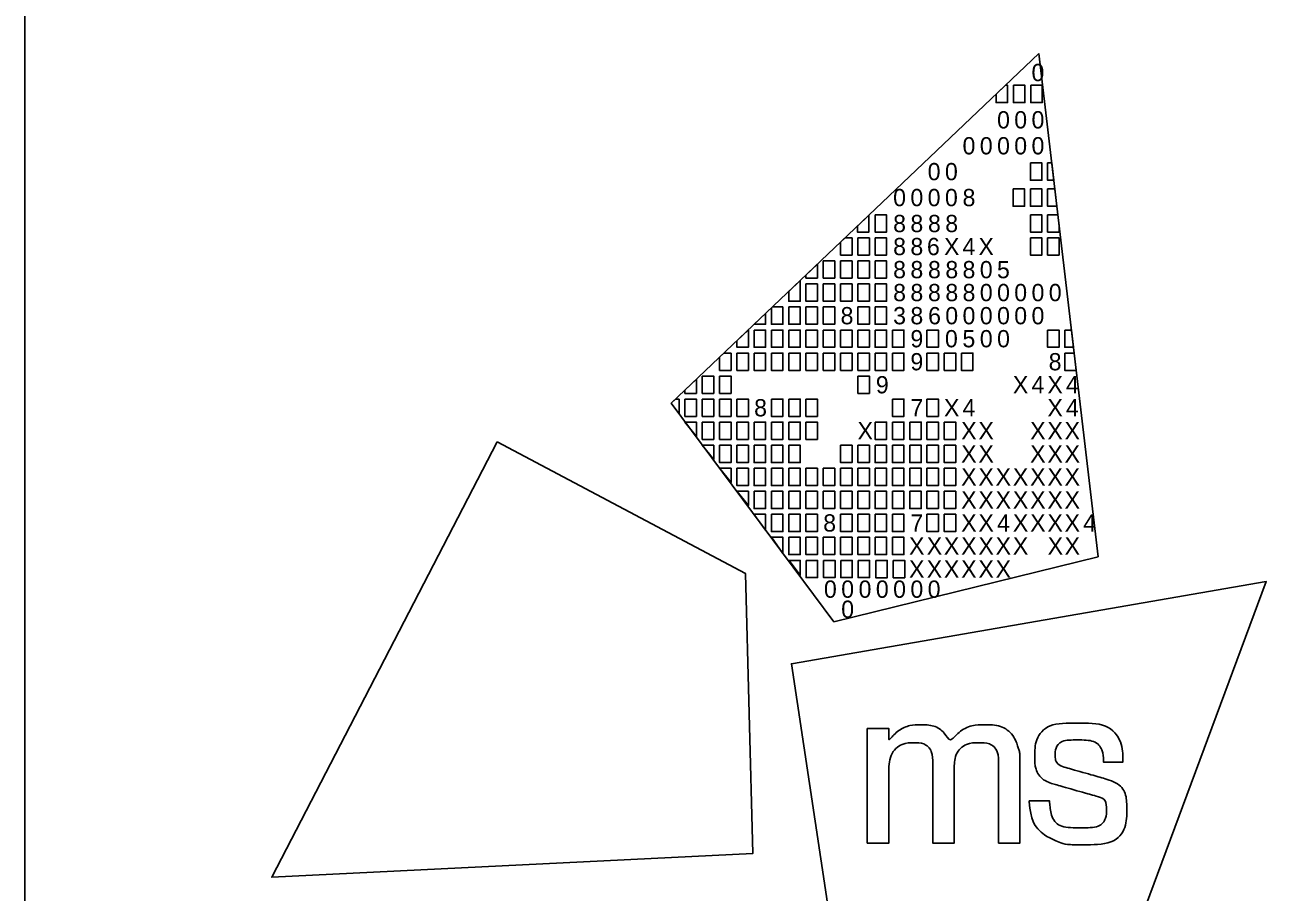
# Model space of a CAD drawing. Extents: x 0 to 34, y 0 to 22.
# Drawn here: x 32 to 33.186, y 3.285 to 4.114 of the extents above; entities that cross this region are included whole.
import ezdxf

# ---------------------------------------------------------------- set-up
doc = ezdxf.new("R2010")
doc.units = 0
doc.layers.add('SH_Border', color=7, linetype='Continuous')
doc.layers.add('SH_Data', color=7, linetype='Continuous')

msp = doc.modelspace()

# ---------------------------------------------------------------- linework, layer by layer
at = {"layer": 'SH_Border'}
msp.add_line((32, 0.5), (32, 21.5), dxfattribs=at)
at = {"layer": 'SH_Data'}
for p, q in [((32.6175, 3.7519), (32.9688, 4.0861)), ((32.9688, 4.0861), (32.9688, 4.0861)), ((32.9688, 4.0861), (33.0253, 3.6052)), ((32.773, 3.543), (32.6175, 3.7519)), ((33.0253, 3.6052), (32.773, 3.543)), ((32.75, 3.5), (32.75, 3.5))]:
    msp.add_line(p, q, dxfattribs=at)
for points in [[(32.9279, 4.0472), (32.9369, 4.0558), (32.9389, 4.0558), (32.9389, 4.0393), (32.9279, 4.0393)], [(32.9444, 4.0558), (32.9554, 4.0558), (32.9554, 4.0393), (32.9444, 4.0393)], [(32.9609, 4.0558), (32.9719, 4.0558), (32.9719, 4.0393), (32.9609, 4.0393)], [(32.9606, 3.9815), (32.9716, 3.9815), (32.9716, 3.965), (32.9606, 3.965)], [(32.9771, 3.9815), (32.9811, 3.9815), (32.983, 3.965), (32.9771, 3.965)], [(32.9441, 3.9567), (32.9551, 3.9567), (32.9551, 3.9402), (32.9441, 3.9402)], [(32.9606, 3.9567), (32.9716, 3.9567), (32.9716, 3.9402), (32.9606, 3.9402)], [(32.9771, 3.9567), (32.984, 3.9567), (32.9859, 3.9402), (32.9771, 3.9402)], [(32.7953, 3.9211), (32.8064, 3.9316), (32.8064, 3.9154), (32.7953, 3.9154)], [(32.8123, 3.9319), (32.8233, 3.9319), (32.8233, 3.9154), (32.8123, 3.9154)], [(32.9606, 3.9319), (32.9716, 3.9319), (32.9716, 3.9154), (32.9606, 3.9154)], [(32.9771, 3.9319), (32.9869, 3.9319), (32.9881, 3.9218), (32.9881, 3.9154), (32.9771, 3.9154)], [(32.7958, 3.9099), (32.8068, 3.9099), (32.8068, 3.8934), (32.7958, 3.8934)], [(32.8123, 3.9099), (32.8233, 3.9099), (32.8233, 3.8934), (32.8123, 3.8934)], [(32.9606, 3.9099), (32.9716, 3.9099), (32.9716, 3.8934), (32.9606, 3.8934)], [(32.9771, 3.9099), (32.9881, 3.9099), (32.9881, 3.8934), (32.9771, 3.8934)], [(32.7627, 3.8879), (32.7737, 3.8879), (32.7737, 3.8714), (32.7627, 3.8714)], [(32.7793, 3.8879), (32.7903, 3.8879), (32.7903, 3.8714), (32.7793, 3.8714)], [(32.7958, 3.8879), (32.8068, 3.8879), (32.8068, 3.8714), (32.7958, 3.8714)], [(32.8123, 3.8879), (32.8233, 3.8879), (32.8233, 3.8714), (32.8123, 3.8714)], [(32.7462, 3.8659), (32.7572, 3.8659), (32.7572, 3.8494), (32.7462, 3.8494)], [(32.7627, 3.8659), (32.7737, 3.8659), (32.7737, 3.8494), (32.7627, 3.8494)], [(32.7793, 3.8659), (32.7903, 3.8659), (32.7903, 3.8494), (32.7793, 3.8494)], [(32.7958, 3.8659), (32.8068, 3.8659), (32.8068, 3.8494), (32.7958, 3.8494)], [(32.8123, 3.8659), (32.8233, 3.8659), (32.8233, 3.8494), (32.8123, 3.8494)], [(32.7297, 3.8439), (32.7407, 3.8439), (32.7407, 3.8273), (32.7297, 3.8273)], [(32.7462, 3.8439), (32.7572, 3.8439), (32.7572, 3.8273), (32.7462, 3.8273)], [(32.7627, 3.8439), (32.7737, 3.8439), (32.7737, 3.8273), (32.7627, 3.8273)], [(32.7958, 3.8439), (32.8068, 3.8439), (32.8068, 3.8273), (32.7958, 3.8273)], [(32.8123, 3.8439), (32.8233, 3.8439), (32.8233, 3.8273), (32.8123, 3.8273)], [(32.6967, 3.8218), (32.7077, 3.8218), (32.7077, 3.8053), (32.6967, 3.8053)], [(32.7132, 3.8218), (32.7242, 3.8218), (32.7242, 3.8053), (32.7132, 3.8053)], [(32.7297, 3.8218), (32.7407, 3.8218), (32.7407, 3.8053), (32.7297, 3.8053)], [(32.7462, 3.8218), (32.7572, 3.8218), (32.7572, 3.8053), (32.7462, 3.8053)], [(32.7627, 3.8218), (32.7737, 3.8218), (32.7737, 3.8053), (32.7627, 3.8053)], [(32.7793, 3.8218), (32.7903, 3.8218), (32.7903, 3.8053), (32.7793, 3.8053)], [(32.7958, 3.8218), (32.8068, 3.8218), (32.8068, 3.8053), (32.7958, 3.8053)], [(32.8123, 3.8218), (32.8233, 3.8218), (32.8233, 3.8053), (32.8123, 3.8053)], [(32.8288, 3.8218), (32.8398, 3.8218), (32.8398, 3.8053), (32.8288, 3.8053)], [(32.8618, 3.8218), (32.8728, 3.8218), (32.8728, 3.8053), (32.8618, 3.8053)], [(32.9771, 3.8218), (32.9881, 3.8218), (32.9881, 3.8053), (32.9771, 3.8053)], [(32.9935, 3.8218), (32.9998, 3.8218), (33.0018, 3.8053), (32.9935, 3.8053)], [(32.6802, 3.7998), (32.6912, 3.7998), (32.6912, 3.7833), (32.6802, 3.7833)], [(32.6967, 3.7998), (32.7077, 3.7998), (32.7077, 3.7833), (32.6967, 3.7833)], [(32.7132, 3.7998), (32.7242, 3.7998), (32.7242, 3.7833), (32.7132, 3.7833)], [(32.7297, 3.7998), (32.7407, 3.7998), (32.7407, 3.7833), (32.7297, 3.7833)], [(32.7462, 3.7998), (32.7572, 3.7998), (32.7572, 3.7833), (32.7462, 3.7833)], [(32.7627, 3.7998), (32.7737, 3.7998), (32.7737, 3.7833), (32.7627, 3.7833)], [(32.7793, 3.7998), (32.7903, 3.7998), (32.7903, 3.7833), (32.7793, 3.7833)], [(32.7958, 3.7998), (32.8068, 3.7998), (32.8068, 3.7833), (32.7958, 3.7833)], [(32.8123, 3.7998), (32.8233, 3.7998), (32.8233, 3.7833), (32.8123, 3.7833)], [(32.8288, 3.7998), (32.8398, 3.7998), (32.8398, 3.7833), (32.8288, 3.7833)], [(32.8618, 3.7998), (32.8728, 3.7998), (32.8728, 3.7833), (32.8618, 3.7833)], [(32.8783, 3.7998), (32.8893, 3.7998), (32.8893, 3.7833), (32.8783, 3.7833)], [(32.8947, 3.7998), (32.9057, 3.7998), (32.9057, 3.7833), (32.8947, 3.7833)], [(32.9935, 3.7998), (33.0024, 3.7998), (33.0044, 3.7833), (32.9935, 3.7833)], [(32.6471, 3.7778), (32.6581, 3.7778), (32.6581, 3.7613), (32.6471, 3.7613)], [(32.6637, 3.7778), (32.6747, 3.7778), (32.6747, 3.7613), (32.6637, 3.7613)], [(32.7958, 3.7778), (32.8068, 3.7778), (32.8068, 3.7613), (32.7958, 3.7613)], [(32.6306, 3.7558), (32.6416, 3.7558), (32.6416, 3.7393), (32.6306, 3.7393)], [(32.6471, 3.7558), (32.6581, 3.7558), (32.6581, 3.7393), (32.6471, 3.7393)], [(32.6637, 3.7558), (32.6747, 3.7558), (32.6747, 3.7393), (32.6637, 3.7393)], [(32.6802, 3.7558), (32.6912, 3.7558), (32.6912, 3.7393), (32.6802, 3.7393)], [(32.7132, 3.7558), (32.7242, 3.7558), (32.7242, 3.7393), (32.7132, 3.7393)], [(32.7297, 3.7558), (32.7407, 3.7558), (32.7407, 3.7393), (32.7297, 3.7393)], [(32.7462, 3.7558), (32.7572, 3.7558), (32.7572, 3.7393), (32.7462, 3.7393)], [(32.8288, 3.7558), (32.8398, 3.7558), (32.8398, 3.7393), (32.8288, 3.7393)], [(32.8618, 3.7558), (32.8728, 3.7558), (32.8728, 3.7393), (32.8618, 3.7393)], [(32.6306, 3.7338), (32.6416, 3.7338), (32.6416, 3.72)], [(32.6471, 3.7338), (32.6581, 3.7338), (32.6581, 3.7173), (32.6471, 3.7173)], [(32.6637, 3.7338), (32.6747, 3.7338), (32.6747, 3.7173), (32.6637, 3.7173)], [(32.6802, 3.7338), (32.6912, 3.7338), (32.6912, 3.7173), (32.6802, 3.7173)], [(32.6967, 3.7338), (32.7077, 3.7338), (32.7077, 3.7173), (32.6967, 3.7173)], [(32.7132, 3.7338), (32.7242, 3.7338), (32.7242, 3.7173), (32.7132, 3.7173)], [(32.7297, 3.7338), (32.7407, 3.7338), (32.7407, 3.7173), (32.7297, 3.7173)], [(32.7462, 3.7338), (32.7572, 3.7338), (32.7572, 3.7173), (32.7462, 3.7173)], [(32.8123, 3.7338), (32.8233, 3.7338), (32.8233, 3.7173), (32.8123, 3.7173)], [(32.8288, 3.7338), (32.8398, 3.7338), (32.8398, 3.7173), (32.8288, 3.7173)], [(32.8453, 3.7338), (32.8563, 3.7338), (32.8563, 3.7173), (32.8453, 3.7173)], [(32.8618, 3.7338), (32.8728, 3.7338), (32.8728, 3.7173), (32.8618, 3.7173)], [(32.8783, 3.7338), (32.8893, 3.7338), (32.8893, 3.7173), (32.8783, 3.7173)], [(32.6471, 3.7117), (32.6581, 3.7117), (32.6581, 3.698)], [(32.6637, 3.7117), (32.6747, 3.7117), (32.6747, 3.6952), (32.6637, 3.6952)], [(32.6802, 3.7117), (32.6912, 3.7117), (32.6912, 3.6952), (32.6802, 3.6952)], [(32.6967, 3.7117), (32.7077, 3.7117), (32.7077, 3.6952), (32.6967, 3.6952)], [(32.7132, 3.7117), (32.7242, 3.7117), (32.7242, 3.6952), (32.7132, 3.6952)], [(32.7297, 3.7117), (32.7407, 3.7117), (32.7407, 3.6952), (32.7297, 3.6952)], [(32.7793, 3.7117), (32.7903, 3.7117), (32.7903, 3.6952), (32.7793, 3.6952)], [(32.7958, 3.7117), (32.8068, 3.7117), (32.8068, 3.6952), (32.7958, 3.6952)], [(32.8123, 3.7117), (32.8233, 3.7117), (32.8233, 3.6952), (32.8123, 3.6952)], [(32.8288, 3.7117), (32.8398, 3.7117), (32.8398, 3.6952), (32.8288, 3.6952)], [(32.8453, 3.7117), (32.8563, 3.7117), (32.8563, 3.6952), (32.8453, 3.6952)], [(32.8618, 3.7117), (32.8728, 3.7117), (32.8728, 3.6952), (32.8618, 3.6952)], [(32.8783, 3.7117), (32.8893, 3.7117), (32.8893, 3.6952), (32.8783, 3.6952)], [(32.6637, 3.6897), (32.6747, 3.6897), (32.6747, 3.676)], [(32.6747, 3.6897), (32.6747, 3.6897), (32.6747, 3.6897)], [(32.6802, 3.6897), (32.6912, 3.6897), (32.6912, 3.6732), (32.6802, 3.6732)], [(32.6967, 3.6897), (32.7077, 3.6897), (32.7077, 3.6732), (32.6967, 3.6732)], [(32.7132, 3.6897), (32.7242, 3.6897), (32.7242, 3.6732), (32.7132, 3.6732)], [(32.7297, 3.6897), (32.7407, 3.6897), (32.7407, 3.6732), (32.7297, 3.6732)], [(32.7462, 3.6897), (32.7572, 3.6897), (32.7572, 3.6732), (32.7462, 3.6732)], [(32.7627, 3.6897), (32.7737, 3.6897), (32.7737, 3.6732), (32.7627, 3.6732)], [(32.7793, 3.6897), (32.7903, 3.6897), (32.7903, 3.6732), (32.7793, 3.6732)], [(32.7958, 3.6897), (32.8068, 3.6897), (32.8068, 3.6732), (32.7958, 3.6732)], [(32.8123, 3.6897), (32.8233, 3.6897), (32.8233, 3.6732), (32.8123, 3.6732)], [(32.8288, 3.6897), (32.8398, 3.6897), (32.8398, 3.6732), (32.8288, 3.6732)], [(32.8453, 3.6897), (32.8563, 3.6897), (32.8563, 3.6732), (32.8453, 3.6732)], [(32.8618, 3.6897), (32.8728, 3.6897), (32.8728, 3.6732), (32.8618, 3.6732)], [(32.8783, 3.6897), (32.8893, 3.6897), (32.8893, 3.6732), (32.8783, 3.6732)], [(32.6802, 3.6677), (32.6912, 3.6677), (32.6912, 3.654)], [(32.6967, 3.6677), (32.7077, 3.6677), (32.7077, 3.6512), (32.6967, 3.6512)], [(32.7132, 3.6677), (32.7242, 3.6677), (32.7242, 3.6512), (32.7132, 3.6512)], [(32.7297, 3.6677), (32.7407, 3.6677), (32.7407, 3.6512), (32.7297, 3.6512)], [(32.7462, 3.6677), (32.7572, 3.6677), (32.7572, 3.6512), (32.7462, 3.6512)], [(32.7627, 3.6677), (32.7737, 3.6677), (32.7737, 3.6512), (32.7627, 3.6512)], [(32.7793, 3.6677), (32.7903, 3.6677), (32.7903, 3.6512), (32.7793, 3.6512)], [(32.7958, 3.6677), (32.8068, 3.6677), (32.8068, 3.6512), (32.7958, 3.6512)], [(32.8123, 3.6677), (32.8233, 3.6677), (32.8233, 3.6512), (32.8123, 3.6512)], [(32.8288, 3.6677), (32.8398, 3.6677), (32.8398, 3.6512), (32.8288, 3.6512)], [(32.8453, 3.6677), (32.8563, 3.6677), (32.8563, 3.6512), (32.8453, 3.6512)], [(32.8618, 3.6677), (32.8728, 3.6677), (32.8728, 3.6512), (32.8618, 3.6512)], [(32.8783, 3.6677), (32.8893, 3.6677), (32.8893, 3.6512), (32.8783, 3.6512)], [(32.7077, 3.6305), (32.6965, 3.6457), (32.7077, 3.6457)], [(32.7132, 3.6457), (32.7242, 3.6457), (32.7242, 3.6292), (32.7132, 3.6292)], [(32.7297, 3.6457), (32.7407, 3.6457), (32.7407, 3.6292), (32.7297, 3.6292)], [(32.7462, 3.6457), (32.7572, 3.6457), (32.7572, 3.6292), (32.7462, 3.6292)], [(32.7793, 3.6457), (32.7903, 3.6457), (32.7903, 3.6292), (32.7793, 3.6292)], [(32.7958, 3.6457), (32.8068, 3.6457), (32.8068, 3.6292), (32.7958, 3.6292)], [(32.8123, 3.6457), (32.8233, 3.6457), (32.8233, 3.6292), (32.8123, 3.6292)], [(32.8288, 3.6457), (32.8398, 3.6457), (32.8398, 3.6292), (32.8288, 3.6292)], [(32.8618, 3.6457), (32.8728, 3.6457), (32.8728, 3.6292), (32.8618, 3.6292)], [(32.8783, 3.6457), (32.8893, 3.6457), (32.8893, 3.6292), (32.8783, 3.6292)], [(32.724, 3.6082), (32.7132, 3.6237), (32.7242, 3.6237)], [(32.7297, 3.6237), (32.7407, 3.6237), (32.7407, 3.6072), (32.7297, 3.6072)], [(32.7462, 3.6237), (32.7572, 3.6237), (32.7572, 3.6072), (32.7462, 3.6072)], [(32.7627, 3.6237), (32.7737, 3.6237), (32.7737, 3.6072), (32.7627, 3.6072)], [(32.7793, 3.6237), (32.7903, 3.6237), (32.7903, 3.6072), (32.7793, 3.6072)], [(32.7958, 3.6237), (32.8068, 3.6237), (32.8068, 3.6072), (32.7958, 3.6072)], [(32.8123, 3.6237), (32.8233, 3.6237), (32.8233, 3.6072), (32.8123, 3.6072)], [(32.8288, 3.6237), (32.8398, 3.6237), (32.8398, 3.6072), (32.8288, 3.6072)], [(32.7302, 3.6017), (32.7407, 3.6017), (32.7408, 3.5875)], [(32.7463, 3.6017), (32.7573, 3.6017), (32.7573, 3.5852), (32.7463, 3.5852)], [(32.763, 3.6017), (32.774, 3.6017), (32.774, 3.5852), (32.763, 3.5852)], [(32.7794, 3.6017), (32.7904, 3.6017), (32.7904, 3.5852), (32.7794, 3.5852)], [(32.796, 3.6017), (32.807, 3.6017), (32.807, 3.5852), (32.796, 3.5852)], [(32.8129, 3.6017), (32.8239, 3.6017), (32.8239, 3.5851), (32.8129, 3.5851)], [(32.8296, 3.6017), (32.8406, 3.6017), (32.8406, 3.5851), (32.8296, 3.5851)]]:
    msp.add_lwpolyline(points, close=True, dxfattribs=at)
for points in [[(32.7903, 3.9099), (32.7836, 3.9099), (32.7793, 3.9058), (32.7793, 3.8934), (32.7903, 3.8934), (32.7903, 3.9099)], [(32.7572, 3.8849), (32.7462, 3.8744), (32.7462, 3.8714), (32.7572, 3.8714), (32.7572, 3.8849)], [(32.7407, 3.8691), (32.7297, 3.8587), (32.7297, 3.8494), (32.7407, 3.8494), (32.7407, 3.8691)], [(32.7242, 3.8439), (32.7141, 3.8439), (32.7132, 3.843), (32.7132, 3.8273), (32.7242, 3.8273), (32.7242, 3.8439)], [(32.7077, 3.8377), (32.6968, 3.8273), (32.7077, 3.8273), (32.7077, 3.8377)], [(32.6912, 3.822), (32.6802, 3.8115), (32.6802, 3.8053), (32.6912, 3.8053), (32.6912, 3.822)], [(32.6747, 3.7998), (32.6679, 3.7998), (32.6637, 3.7958), (32.6637, 3.7833), (32.6747, 3.7833), (32.6747, 3.7998)], [(32.6416, 3.7749), (32.6306, 3.7644), (32.6306, 3.7613), (32.6416, 3.7613), (32.6416, 3.7749)], [(32.6251, 3.7558), (32.6216, 3.7558), (32.6175, 3.7519), (32.6251, 3.7417), (32.6251, 3.7558)], [(32.4512, 3.7149), (32.2359, 3.2988), (32.6956, 3.3215), (32.6884, 3.5892), (32.4512, 3.7149)], [(33.0229, 3.1422), (33.1859, 3.5814), (32.7324, 3.5029), (32.7722, 3.2381), (33.0229, 3.1422)]]:
    msp.add_lwpolyline(points, dxfattribs=at)
for points in [[(32.8048, 3.3315), (32.8048, 3.3315), (32.8048, 3.4409), (32.8048, 3.4409), (32.8048, 3.4409), (32.8255, 3.4409), (32.8255, 3.4409), (32.8255, 3.4409), (32.8255, 3.4297), (32.8255, 3.4297), (32.8346, 3.4399), (32.8457, 3.4445), (32.8555, 3.4445), (32.8688, 3.4445), (32.8791, 3.4372), (32.8837, 3.4266), (32.8915, 3.4381), (32.905, 3.4446), (32.9166, 3.4446), (32.9325, 3.4446), (32.9451, 3.435), (32.9494, 3.4213), (32.9494, 3.4212), (32.9494, 3.4212), (32.9494, 3.4212), (32.9501, 3.419), (32.9506, 3.4172), (32.9506, 3.4071), (32.9506, 3.4071), (32.9506, 3.3314), (32.9506, 3.3314), (32.9506, 3.3314), (32.9303, 3.3314), (32.9303, 3.3314), (32.9303, 3.3314), (32.9303, 3.4048), (32.9303, 3.4048), (32.9303, 3.4201), (32.9219, 3.4274), (32.911, 3.4274), (32.8995, 3.4274), (32.8879, 3.4171), (32.8879, 3.4001), (32.8879, 3.4001), (32.8879, 3.3315), (32.8879, 3.3315), (32.8879, 3.3315), (32.8674, 3.3315), (32.8674, 3.3315), (32.8674, 3.3315), (32.8674, 3.4059), (32.8674, 3.4059), (32.8674, 3.4203), (32.8588, 3.4274), (32.8496, 3.4274), (32.8384, 3.4274), (32.8254, 3.417), (32.8254, 3.3962), (32.8254, 3.3962), (32.8254, 3.3315), (32.8254, 3.3315), (32.8254, 3.3315), (32.8048, 3.3315), (32.8048, 3.3315)], [(32.9595, 3.3709), (32.9595, 3.3709), (32.9595, 3.3717), (32.9595, 3.3717), (32.9595, 3.3717), (32.9603, 3.3717), (32.9603, 3.3717), (32.9603, 3.3717), (32.9783, 3.3717), (32.9783, 3.3717), (32.9783, 3.3717), (32.9789, 3.3717), (32.9789, 3.3717), (32.9789, 3.3717), (32.979, 3.371), (32.979, 3.371), (32.9803, 3.3554), (32.9887, 3.346), (33.009, 3.346), (33.0273, 3.346), (33.0333, 3.3554), (33.0333, 3.3631), (33.0333, 3.3732), (33.0256, 3.3758), (33.0175, 3.378), (33.0175, 3.378), (32.987, 3.3867), (32.987, 3.3867), (32.972, 3.3909), (32.9648, 3.4019), (32.9648, 3.4142), (32.9648, 3.4303), (32.9768, 3.4462), (33.0052, 3.4462), (33.0348, 3.4462), (33.0489, 3.4285), (33.0489, 3.4095), (33.0489, 3.4095), (33.0489, 3.4087), (33.0489, 3.4087), (33.0489, 3.4087), (33.0482, 3.4087), (33.0482, 3.4087), (33.0482, 3.4087), (33.0312, 3.4087), (33.0312, 3.4087), (33.0312, 3.4087), (33.0305, 3.4087), (33.0305, 3.4087), (33.0305, 3.4087), (33.0305, 3.4094), (33.0305, 3.4094), (33.0301, 3.4208), (33.0226, 3.43), (33.0056, 3.43), (32.9891, 3.43), (32.9843, 3.4218), (32.9843, 3.4157), (32.9843, 3.4108), (32.9869, 3.4059), (32.9959, 3.4033), (32.9959, 3.4033), (33.0255, 3.3948), (33.0255, 3.3948), (33.0462, 3.3889), (33.0527, 3.3777), (33.0527, 3.3639), (33.0527, 3.3462), (33.041, 3.3298), (33.0087, 3.3298), (32.9952, 3.3298), (32.9877, 3.3321), (32.9823, 3.3348), (32.969, 3.3414), (32.9609, 3.3536), (32.9595, 3.3709)]]:
    msp.add_open_spline(points, degree=3, dxfattribs=at)

# ---------------------------------------------------------------- texts
for s, p in [('0', (32.9617, 4.0597)), ('0', (32.9288, 4.0145)), ('0', (32.9452, 4.0145)), ('0', (32.9617, 4.0145)), ('0', (32.8958, 3.9897)), ('0', (32.9123, 3.9897)), ('0', (32.9288, 3.9897)), ('0', (32.9452, 3.9897)), ('0', (32.9617, 3.9897)), ('0', (32.8625, 3.965)), ('0', (32.879, 3.965)), ('0', (32.8295, 3.9402)), ('0', (32.846, 3.9402)), ('0', (32.8625, 3.9402)), ('0', (32.879, 3.9402)), ('8', (32.8958, 3.9402)), ('8', (32.8295, 3.9154)), ('8', (32.846, 3.9154)), ('8', (32.8628, 3.9154)), ('8', (32.8793, 3.9154)), ('8', (32.8295, 3.8934)), ('8', (32.846, 3.8934)), ('6', (32.8618, 3.8934)), ('X', (32.8781, 3.8934)), ('4', (32.8958, 3.8934)), ('X', (32.911, 3.8934)), ('8', (32.8295, 3.8713)), ('8', (32.846, 3.8713)), ('8', (32.8628, 3.8713)), ('8', (32.8794, 3.8713)), ('8', (32.8958, 3.8713)), ('0', (32.9123, 3.8713)), ('5', (32.9287, 3.8713)), ('8', (32.8295, 3.8494)), ('8', (32.846, 3.8494)), ('8', (32.8628, 3.8494)), ('8', (32.8794, 3.8494)), ('8', (32.8958, 3.8494)), ('0', (32.9123, 3.8494)), ('0', (32.9288, 3.8494)), ('0', (32.9452, 3.8494)), ('0', (32.9617, 3.8494)), ('0', (32.9782, 3.8494)), ('8', (32.7793, 3.8273)), ('3', (32.8295, 3.8273)), ('8', (32.846, 3.8273)), ('6', (32.8629, 3.8273)), ('0', (32.8793, 3.8273)), ('0', (32.8958, 3.8273)), ('0', (32.9123, 3.8273)), ('0', (32.9288, 3.8273)), ('0', (32.9452, 3.8273)), ('0', (32.9617, 3.8273)), ('9', (32.846, 3.8053)), ('0', (32.879, 3.8053)), ('5', (32.8957, 3.8053)), ('0', (32.9123, 3.8053)), ('0', (32.9288, 3.8053)), ('9', (32.846, 3.7833)), ('8', (32.9781, 3.7833)), ('9', (32.813, 3.7613)), ('X', (32.9439, 3.7613)), ('4', (32.9617, 3.7613)), ('X', (32.9769, 3.7613)), ('4', (32.9946, 3.7613)), ('8', (32.6967, 3.7393)), ('7', (32.846, 3.7393)), ('X', (32.8781, 3.7393)), ('4', (32.8958, 3.7393)), ('X', (32.9769, 3.7393)), ('4', (32.9946, 3.7393)), ('X', (32.7955, 3.7173)), ('X', (32.8945, 3.7173)), ('X', (32.911, 3.7173)), ('X', (32.9604, 3.7173)), ('X', (32.9769, 3.7173)), ('X', (32.9933, 3.7173)), ('X', (32.8945, 3.6952)), ('X', (32.911, 3.6952)), ('X', (32.9604, 3.6952)), ('X', (32.9769, 3.6952)), ('X', (32.9933, 3.6952)), ('X', (32.8945, 3.6732)), ('X', (32.911, 3.6732)), ('X', (32.9274, 3.6732)), ('X', (32.9439, 3.6732)), ('X', (32.9604, 3.6732)), ('X', (32.9769, 3.6732)), ('X', (32.9933, 3.6732)), ('X', (32.8945, 3.6512)), ('X', (32.911, 3.6512)), ('X', (32.9274, 3.6512)), ('X', (32.9439, 3.6512)), ('X', (32.9604, 3.6512)), ('X', (32.9769, 3.6512)), ('X', (32.9933, 3.6512)), ('8', (32.7627, 3.6292)), ('7', (32.846, 3.6292)), ('X', (32.8945, 3.6292)), ('X', (32.911, 3.6292)), ('4', (32.9288, 3.6292)), ('X', (32.9439, 3.6292)), ('X', (32.9604, 3.6292)), ('X', (32.9769, 3.6292)), ('X', (32.9933, 3.6292)), ('4', (33.0111, 3.6292)), ('X', (32.8447, 3.6072)), ('X', (32.8616, 3.6072)), ('X', (32.878, 3.6072)), ('X', (32.8945, 3.6072)), ('X', (32.911, 3.6072)), ('X', (32.9274, 3.6072)), ('X', (32.9439, 3.6072)), ('X', (32.9771, 3.6072)), ('X', (32.9933, 3.6072)), ('X', (32.8447, 3.5851)), ('X', (32.8616, 3.5851)), ('X', (32.878, 3.5851)), ('X', (32.8945, 3.5851)), ('X', (32.911, 3.5851)), ('X', (32.9274, 3.5851)), ('0', (32.7634, 3.5659)), ('0', (32.7799, 3.5659)), ('0', (32.7965, 3.5659)), ('0', (32.813, 3.5659)), ('0', (32.8295, 3.5659)), ('0', (32.846, 3.5659)), ('0', (32.8625, 3.5659)), ('0', (32.7799, 3.5467))]:
    msp.add_text(s, height=0.0165, rotation=360, dxfattribs=at).set_placement(p)

doc.saveas('drawing.dxf')
